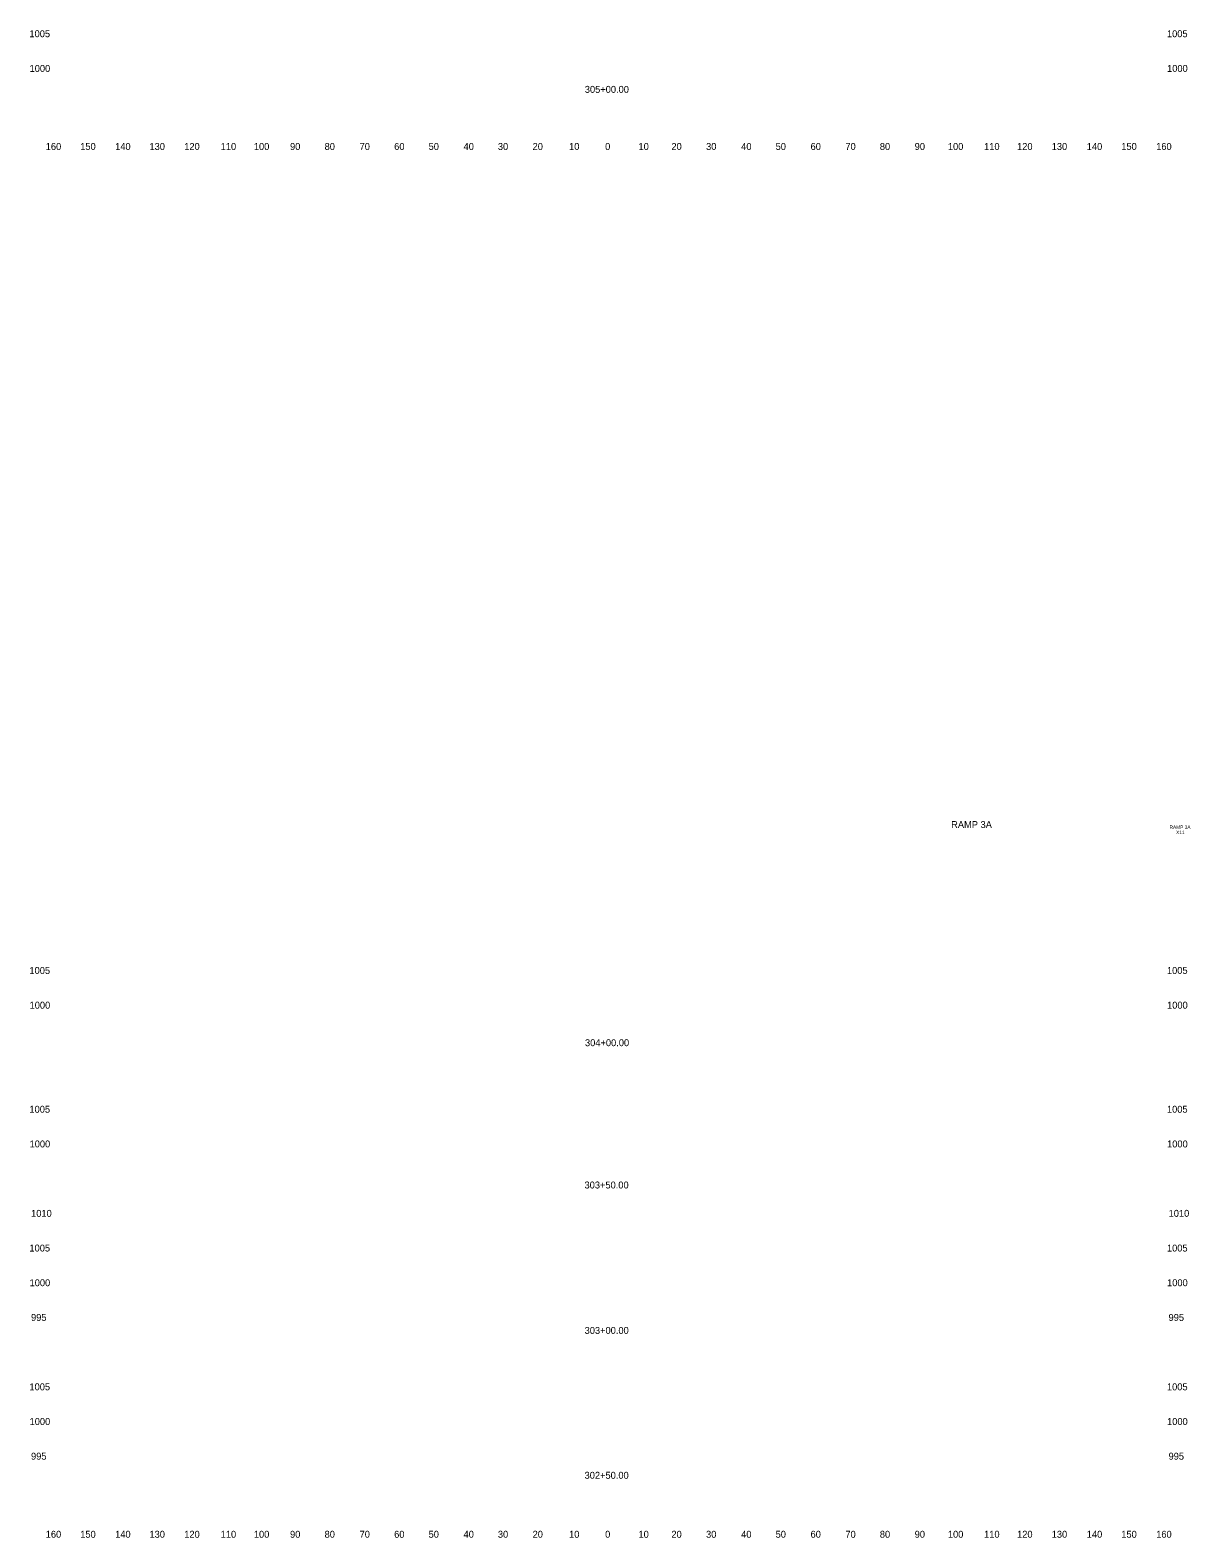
# Model space of a CAD drawing. Extents: x 4286 to 5843, y 4997 to 8804.
# Drawn here: x 5508.6 to 5842.8, y 4997.5 to 5432 of the extents above; entities that cross this region are included whole.
import ezdxf

# ---------------------------------------------------------------- set-up
doc = ezdxf.new("R2010")
doc.units = 0
for name, color, linetype in [('RD_SHT_ID', 7, 'Continuous'), ('RD_XS_TX_Offset', 7, 'Continuous'), ('RD_XS_TX_Station', 7, 'Continuous')]:
    doc.layers.add(name, color=color, linetype=linetype)

msp = doc.modelspace()

# ---------------------------------------------------------------- texts
at = {"layer": 'RD_SHT_ID'}
for s, height, p in [('RAMP 3A', 2, (5774.02, 5202.06)), ('RAMP 3A', 1, (5836.93, 5201.8)), ('X11', 1, (5838.85, 5200.3))]:
    msp.add_text(s, height=height, dxfattribs=at).set_placement(p)
at = {"layer": 'RD_XS_TX_Offset'}
for s, p in [('1005', (5508.4, 5430)), ('1005', (5836.2, 5430)), ('1000', (5508.44, 5420)), ('1000', (5836.24, 5420)), ('160', (5513.1, 5397.5)), ('150', (5523.04, 5397.5)), ('140', (5533.1, 5397.5)), ('130', (5542.99, 5397.5)), ('120', (5553.01, 5397.5)), ('110', (5563.51, 5397.5)), ('100', (5573.07, 5397.5)), ('90', (5583.5, 5397.5)), ('80', (5593.46, 5397.5)), ('70', (5603.54, 5397.5)), ('60', (5613.5, 5397.5)), ('50', (5623.43, 5397.5)), ('40', (5633.5, 5397.5)), ('30', (5643.39, 5397.5)), ('20', (5653.4, 5397.5)), ('10', (5663.91, 5397.5)), ('0', (5674.3, 5397.5)), ('0', (5674.3, 5397.5)), ('10', (5683.91, 5397.5)), ('20', (5693.4, 5397.5)), ('30', (5703.39, 5397.5)), ('40', (5713.5, 5397.5)), ('50', (5723.43, 5397.5)), ('60', (5733.5, 5397.5)), ('70', (5743.54, 5397.5)), ('80', (5753.46, 5397.5)), ('90', (5763.5, 5397.5)), ('100', (5773.07, 5397.5)), ('110', (5783.51, 5397.5)), ('120', (5793.01, 5397.5)), ('130', (5802.99, 5397.5)), ('140', (5813.1, 5397.5)), ('150', (5823.04, 5397.5)), ('160', (5833.1, 5397.5)), ('1005', (5508.4, 5160)), ('1005', (5836.2, 5160)), ('1000', (5508.44, 5150)), ('1000', (5836.24, 5150)), ('1005', (5508.4, 5120)), ('1005', (5836.2, 5120)), ('1000', (5508.44, 5110)), ('1000', (5836.24, 5110)), ('1010', (5508.88, 5090)), ('1010', (5836.68, 5090)), ('1005', (5508.4, 5080)), ('1005', (5836.2, 5080)), ('1000', (5508.44, 5070)), ('1000', (5836.24, 5070)), ('995', (5508.86, 5060)), ('995', (5836.66, 5060)), ('1005', (5508.4, 5040)), ('1005', (5836.2, 5040)), ('1000', (5508.44, 5030)), ('1000', (5836.24, 5030)), ('995', (5508.86, 5020)), ('995', (5836.66, 5020)), ('160', (5513.1, 4997.5)), ('150', (5523.04, 4997.5)), ('140', (5533.1, 4997.5)), ('130', (5542.99, 4997.5)), ('120', (5553.01, 4997.5)), ('110', (5563.51, 4997.5)), ('100', (5573.07, 4997.5)), ('90', (5583.5, 4997.5)), ('80', (5593.46, 4997.5)), ('70', (5603.54, 4997.5)), ('60', (5613.5, 4997.5)), ('50', (5623.43, 4997.5)), ('40', (5633.5, 4997.5)), ('30', (5643.39, 4997.5)), ('20', (5653.4, 4997.5)), ('10', (5663.91, 4997.5)), ('0', (5674.3, 4997.5)), ('0', (5674.3, 4997.5)), ('10', (5683.91, 4997.5)), ('20', (5693.4, 4997.5)), ('30', (5703.39, 4997.5)), ('40', (5713.5, 4997.5)), ('50', (5723.43, 4997.5)), ('60', (5733.5, 4997.5)), ('70', (5743.54, 4997.5)), ('80', (5753.46, 4997.5)), ('90', (5763.5, 4997.5)), ('100', (5773.07, 4997.5)), ('110', (5783.51, 4997.5)), ('120', (5793.01, 4997.5)), ('130', (5802.99, 4997.5)), ('140', (5813.1, 4997.5)), ('150', (5823.04, 4997.5)), ('160', (5833.1, 4997.5))]:
    msp.add_text(s, height=2, dxfattribs=at).set_placement(p)
at = {"layer": 'RD_XS_TX_Station'}
for s, p in [('305+00.00', (5668.44, 5413.96)), ('304+00.00', (5668.5, 5139.18)), ('303+50.00', (5668.36, 5098.17)), ('303+00.00', (5668.39, 5056.26)), ('302+50.00', (5668.38, 5014.5))]:
    msp.add_text(s, height=2, dxfattribs=at).set_placement(p)

doc.saveas('drawing.dxf')
